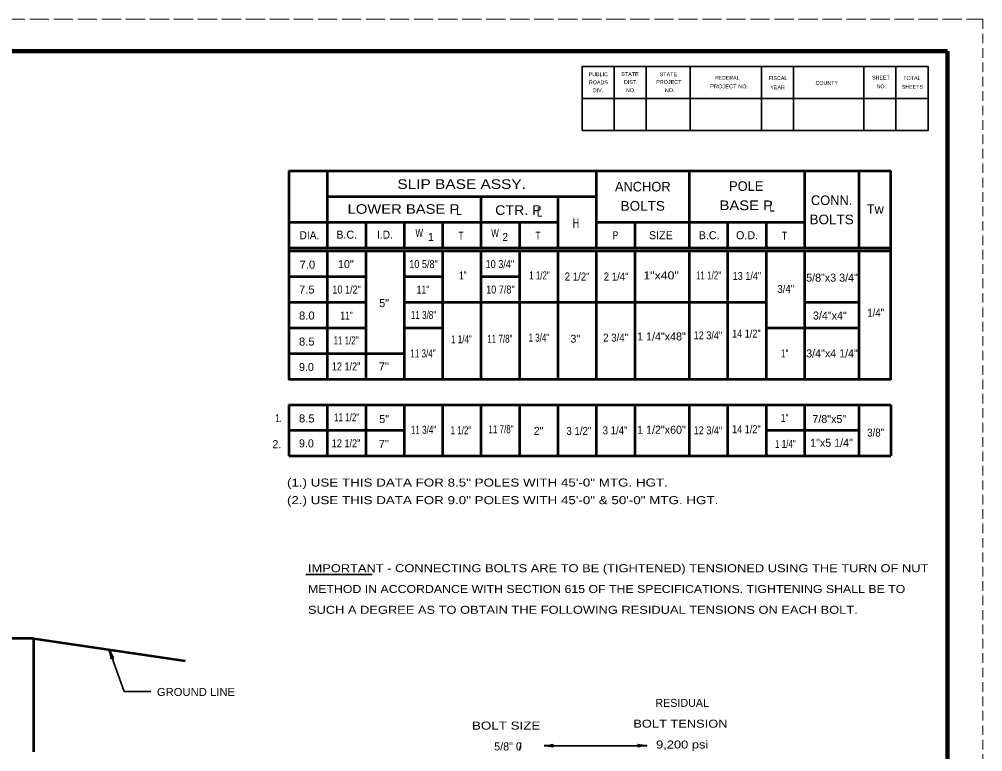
# Model space of a CAD drawing. Extents: x -2 to 678, y 0 to 440.
# Drawn here: x 377.6 to 678.4, y 211.2 to 440 of the extents above; entities that cross this region are included whole.
import ezdxf
from ezdxf.enums import TextEntityAlignment as Align

# ---------------------------------------------------------------- set-up
doc = ezdxf.new("R2010")
doc.units = 0
doc.linetypes.add('LONG_DASHED', pattern=[7.5, 6, -1.5])
doc.linetypes.add('MEDIUM_DASHED', pattern=[4.5, 3, -1.5])
doc.layers.add('1', color=7, linetype='Continuous', lineweight=53)
doc.layers.add('61', color=7, linetype='Continuous', lineweight=35)

msp = doc.modelspace()

# ---------------------------------------------------------------- linework, layer by layer
at = {"layer": '1', "linetype": 'MEDIUM_DASHED', "lineweight": 13}
msp.add_line((678.423, 439.973), (678.403, -0.047), dxfattribs=at)
at = {"layer": '1'}
for p, q in [((461.784, 392.615), (649.784, 392.615)), ((473.784, 392.615), (473.784, 368.615)), ((557.784, 392.615), (557.784, 368.615)), ((586.784, 392.615), (586.784, 368.615)), ((622.784, 392.615), (622.784, 368.615)), ((639.784, 392.615), (639.784, 368.615)), ((473.784, 384.615), (557.784, 384.615)), ((521.784, 384.615), (521.784, 368.615)), ((545.784, 384.615), (545.784, 368.615)), ((461.784, 376.615), (545.784, 376.615)), ((485.784, 376.615), (485.784, 368.615)), ((497.784, 376.615), (497.784, 368.615)), ((509.784, 376.615), (509.784, 368.615)), ((533.784, 376.615), (533.784, 368.615)), ((557.784, 376.615), (622.784, 376.615)), ((569.784, 376.615), (569.784, 368.615)), ((598.784, 376.615), (598.784, 368.615)), ((610.784, 376.615), (610.784, 368.615)), ((461.784, 368.615), (649.784, 368.615)), ((461.784, 367.615), (649.784, 367.615)), ((473.784, 367.615), (473.784, 327.615)), ((485.784, 367.615), (485.784, 327.615)), ((497.784, 367.615), (497.784, 327.615)), ((509.784, 367.615), (509.784, 327.615)), ((521.784, 367.615), (521.784, 327.615)), ((533.784, 367.615), (533.784, 327.615)), ((545.784, 367.615), (545.784, 327.615)), ((557.784, 367.615), (557.784, 327.615)), ((569.784, 367.615), (569.784, 327.615)), ((586.784, 367.615), (586.784, 327.615)), ((598.784, 367.615), (598.784, 327.615)), ((610.784, 367.615), (610.784, 327.615)), ((622.784, 367.615), (622.784, 327.615)), ((639.784, 367.615), (639.784, 327.615)), ((461.784, 359.615), (485.784, 359.615)), ((497.784, 359.615), (509.784, 359.615)), ((521.784, 359.615), (533.784, 359.615)), ((461.784, 351.615), (485.784, 351.615)), ((497.784, 351.615), (610.784, 351.615)), ((622.784, 351.615), (639.784, 351.615)), ((461.784, 343.615), (485.784, 343.615)), ((497.784, 343.615), (509.784, 343.615)), ((610.784, 343.615), (639.784, 343.615)), ((461.784, 319.615), (649.784, 319.615)), ((461.784, 319.615), (461.784, 303.615)), ((473.784, 319.615), (473.784, 303.615)), ((485.784, 319.615), (485.784, 303.615)), ((497.784, 319.615), (497.784, 303.615)), ((509.784, 319.615), (509.784, 303.615)), ((521.784, 319.615), (521.784, 303.615)), ((533.784, 319.615), (533.784, 303.615)), ((545.784, 319.615), (545.784, 303.615)), ((557.784, 319.615), (557.784, 303.615)), ((569.784, 319.615), (569.784, 303.615)), ((586.784, 319.615), (586.784, 303.615)), ((598.784, 319.615), (598.784, 303.615)), ((610.784, 319.615), (610.784, 303.615)), ((622.784, 319.615), (622.784, 303.615)), ((639.784, 319.615), (639.784, 303.615)), ((649.784, 319.615), (649.784, 303.615)), ((461.784, 311.615), (497.784, 311.615)), ((610.784, 311.615), (639.784, 311.615)), ((461.784, 303.615), (649.784, 303.615)), ((382.08, 246.576), (363.472, 246.576)), ((382.08, 246.576), (429.388, 239.606)), ((382.08, 246.576), (382.08, 211.231))]:
    msp.add_line(p, q, dxfattribs=at)
at = {"layer": '1', "lineweight": 35}
for p, q in [((467.139, 266.568), (487.803, 266.568)), ((541.511, 213.123), (573.511, 213.123))]:
    msp.add_line(p, q, dxfattribs=at)
at = {"layer": '1'}
for points in [[(461.784, 392.615), (461.784, 327.615), (649.784, 327.615), (649.784, 392.615)], [(461.784, 335.615), (485.784, 335.615), (497.784, 335.615)]]:
    msp.add_lwpolyline(points, dxfattribs=at)
at = {"layer": '1', "lineweight": 35}
msp.add_lwpolyline([(405.734, 243.091), (410.419, 230.073), (418.7, 230.073)], dxfattribs=at)
at = {"layer": '1', "lineweight": 40}
for centre, major_axis, ratio, start_param, end_param in [((405.914, 241.965), (-0.429, 1.712), 0.07063, 3.1407148, 5.41811), ((406.363, 242.158), (-0.752, 1.627), 0.122415, 0.8963533, 3.1415927), ((542.631, 212.911), (1.756, -0.176), 0.07063, 6.2823074, 8.5597026), ((542.631, 212.911), (1.756, -0.176), 0.07063, 6.2823074, 8.5597026), ((542.602, 213.399), (-1.786, -0.156), 0.122415, 0.8963533, 3.1415927), ((542.602, 213.399), (-1.786, -0.156), 0.122415, 0.8963533, 3.1415927), ((572.42, 212.846), (1.786, 0.156), 0.122415, 0.8963533, 3.1415927), ((572.39, 213.334), (-1.756, 0.176), 0.07063, 6.2823074, 8.5597026)]:
    msp.add_ellipse(centre, major_axis=major_axis, ratio=ratio, start_param=start_param, end_param=end_param, dxfattribs=at)
at = {"layer": '61', "linetype": 'LONG_DASHED', "lineweight": 13}
msp.add_line((-1.597, 439.973), (678.423, 439.973), dxfattribs=at)
at = {"layer": '61', "lineweight": 158}
msp.add_line((667.443, 429.973), (667.463, 9.933), dxfattribs=at)
at = {"layer": '61'}
for p, q in [((563.363, 425.213), (563.363, 405.213)), ((573.363, 425.213), (573.363, 405.213)), ((587.043, 425.213), (587.043, 405.213)), ((609.363, 425.213), (609.363, 405.213)), ((619.363, 425.213), (619.363, 405.213)), ((641.343, 425.233), (641.343, 405.233)), ((651.343, 425.233), (651.343, 405.233)), ((661.363, 415.193), (553.343, 415.213))]:
    msp.add_line(p, q, dxfattribs=at)
at = {"layer": '61', "lineweight": 158}
msp.add_lwpolyline([(667.443, 429.973), (28.403, 429.973), (28.403, 9.953)], dxfattribs=at)
at = {"layer": '61'}
for points in [[(661.343, 425.233), (553.363, 425.213), (553.363, 405.213)], [(661.343, 425.233), (661.343, 405.233), (553.363, 405.213)]]:
    msp.add_lwpolyline(points, dxfattribs=at)

# ---------------------------------------------------------------- texts
at = {"layer": '1'}
for s, height, width, p in [('SLIP BASE ASSY.', 3, 1.2, (495.679, 386.995)), ('LOWER BASE P', 3, 1.15, (480.145, 379.225)), ('L', 3, 0.75, (611.829, 379.931)), ('L', 3, 0.75, (514.037, 378.872)), ('CTR. P', 3, 1.1, (526.217, 378.872)), ('L', 3, 0.75, (539.279, 378.342)), ('H', 3, 0.7, (550.4, 374.81)), ('DIA.', 2.5, 0.95, (465.141, 371.278)), ('I.D.', 2.5, 0.95, (489.324, 371.455)), ('W', 2.5, 0.75, (501.327, 371.984)), ('T', 2.5, 0.8, (514.743, 371.101)), ('W', 2.5, 0.75, (524.981, 371.984)), ('2', 2.5, 0.9, (528.511, 370.748)), ('T', 2.5, 0.8, (538.75, 371.101)), ('P', 2.5, 0.75, (562.933, 371.278)), ('T', 2.5, 0.8, (615.712, 371.101)), ('7.0', 2.5, 1.05, (465.141, 362.095)), ('10 5/8"', 2.5, 0.85, (499.386, 362.271)), ('10 3/4"', 2.5, 0.85, (523.216, 362.271)), ('1"', 2.5, 0.8, (514.919, 358.739)), ('1 1/2"', 2.5, 0.75, (536.808, 358.739)), ('2 1/2"', 2.5, 0.9, (547.929, 358.386)), ('2 1/4"', 2.5, 0.9, (560.108, 358.386)), ('1"x40"', 2.5, 1.15, (572.465, 358.739)), ('11 1/2"', 2.5, 0.75, (588.881, 358.739)), ('13 1/4"', 2.5, 0.85, (600.355, 358.563)), ('7.5', 2.5, 1.05, (464.964, 354.324)), ('10 1/2"', 2.5, 0.85, (475.379, 354.324)), ('11"', 2.5, 0.8, (501.68, 354.324)), ('10 7/8"', 2.5, 0.85, (523.392, 354.324)), ('3/4"', 2.5, 0.9, (614.3, 354.501)), ('11 3/8"', 2.5, 0.75, (499.915, 346.377)), ('1/4"', 2.5, 0.9, (642.367, 347.084)), ('8.0', 2.5, 1.05, (464.964, 346.201)), ('11"', 2.5, 0.8, (477.85, 346.201)), ('14 1/2"', 2.5, 0.85, (600.178, 340.55)), ('8.5', 2.5, 1.05, (464.964, 338.077)), ('11 1/2"', 2.5, 0.75, (475.732, 338.43)), ('1 1/4"', 2.5, 0.75, (512.448, 338.784)), ('11 7/8"', 2.5, 0.75, (523.745, 338.96)), ('1 3/4"', 2.5, 0.75, (536.631, 339.313)), ('2 3/4"', 2.5, 0.9, (559.932, 339.313)), ('12 3/4"', 2.5, 0.85, (588.175, 340.02)), ('11 3/4"', 2.5, 0.75, (499.739, 334.369)), ('1"', 2.5, 0.8, (615.359, 334.369)), ('12 1/2"', 2.5, 0.85, (475.202, 330.307)), ('7"', 2.5, 1.05, (489.854, 330.307)), ('1.', 2.5, 0.65, (457.602, 314.183)), ('8.5', 2.5, 1.05, (464.964, 314.06)), ('11 1/2"', 2.5, 0.75, (475.909, 314.413)), ('1"', 2.5, 0.8, (615.359, 314.236)), ('11 3/4"', 2.5, 0.75, (499.915, 310.528)), ('1 1/2"', 2.5, 0.75, (512.272, 310.351)), ('11 7/8"', 2.5, 0.75, (524.098, 310.704)), ('3 1/4"', 2.5, 0.9, (559.755, 310.351)), ('12 3/4"', 2.5, 0.85, (588.175, 310.351)), ('14 1/2"', 2.5, 0.85, (600.178, 310.704)), ('3 1/2"', 2.5, 0.9, (548.458, 310.174)), ('3/8"', 2.5, 0.9, (642.367, 309.645)), ('12 1/2"', 2.5, 0.85, (475.202, 306.289)), ('7"', 2.5, 1.05, (489.854, 306.113)), ('1 1/4"', 2.5, 0.75, (613.594, 306.113)), ('(1.) USE THIS DATA FOR 8.5" POLES WITH 45\'-0" MTG. HGT.', 2.5, 1.25, (461.204, 294.044)), ('(2.) USE THIS DATA FOR 9.0" POLES WITH 45\'-0" & 50\'-0" MTG. HGT. ', 2.5, 1.25, (461.204, 288.544)), ('IMPORTANT - CONNECTING BOLTS ARE TO BE (TIGHTENED) TENSIONED USING THE TURN OF NUT', 2.5, 1.2, (467.769, 267.303)), ('METHOD IN ACCORDANCE WITH SECTION 615 OF THE SPECIFICATIONS. TIGHTENING SHALL BE TO', 2.5, 1.15, (467.769, 260.803)), ('SUCH A DEGREE AS TO OBTAIN THE FOLLOWING RESIDUAL TENSIONS ON EACH BOLT.', 2.5, 1.2, (467.769, 254.303)), ('GROUND LINE', 2.5, 1.05, (420.593, 228.653))]:
    msp.add_text(s, height=height, dxfattribs=dict(at, width=width)).set_placement(p)
for s, height, p in [('ANCHOR', 3, (572.288, 386.2)), ('POLE', 3, (604.591, 386.376)), ('CONN.', 3, (631.246, 381.961)), ('RESIDUAL', 2.5, (584.594, 225.241)), ('5/8" 0', 2.5, (530.222, 211.639))]:
    msp.add_text(s, height=height, dxfattribs=at).set_placement(p, align=Align.CENTER)
for s, height, width, p in [('BOLTS', 3, 1.05, (572.288, 380.2)), ('BASE P', 3, 1.15, (604.591, 380.376)), ('BOLTS', 3, 1.05, (631.246, 375.961)), ('BOLT SIZE ', 2.5, 1.25, (530.222, 218.139)), ('BOLT TENSION ', 2.5, 1.2, (584.594, 218.741)), ('9,200 psi', 2.5, 1.2, (584.594, 212.241))]:
    msp.add_text(s, height=height, dxfattribs=dict(at, width=width)).set_placement(p, align=Align.CENTER)
for s, height, p in [('Tw', 3, (642.19, 379.225)), ('B.C.', 2.5, (476.615, 371.455)), ('1', 2.5, (505.211, 370.748)), ('SIZE', 2.5, (574.23, 371.278)), ('B.C.', 2.5, (589.764, 371.278)), ('O.D.', 2.5, (601.414, 371.278)), ('10"', 2.5, (477.144, 362.271)), ('5/8"x3 3/4"', 2.5, (623.302, 358.033)), ('5"', 2.5, (490.03, 350.086)), ('3/4"x4"', 2.5, (625.421, 346.201)), ('3"', 2.5, (549.694, 338.96)), ('1 1/4"x48"', 2.5, (570.523, 339.667)), ('3/4"x4 1/4"', 2.5, (623.302, 334.369)), ('9.0', 2.5, (464.964, 330.13)), ('5"', 2.5, (490.03, 313.883)), ('7/8"x5"', 2.5, (625.244, 313.883)), ('1 1/2"x60"', 2.5, (570.523, 310.528)), ('2"', 2.5, (538.22, 310.174)), ('2.', 2.5, (456.654, 306.027)), ('9.0', 2.5, (464.964, 306.289)), ('1"x5 1/4"', 2.5, (624.538, 306.466)), ('/', 2.5, (533.541, 211.576))]:
    msp.add_text(s, height=height, dxfattribs=at).set_placement(p)
at = {"layer": '61'}
for s, rotation, p in [('PUBLIC', 0.033, (555.403, 422.193)), ('FEDERAL', 0.007, (594.863, 421.073)), ('FISCAL', 359.942, (611.603, 421.013)), ('SHEET', 0.059, (643.863, 421.133)), ('ROADS', 0.124, (555.483, 419.673)), ('DIV.', 359.932, (556.683, 417.173)), ('DIST.', 0.056, (566.443, 419.753)), ('YEAR', 0.105, (612.123, 418.113)), ('COUNTY', 0.069, (626.223, 419.473)), ('SHEETS', 359.959, (653.143, 418.293))]:
    msp.add_text(s, height=1.201, rotation=rotation, dxfattribs=at).set_placement(p)
for s, rotation, width, p in [('STATE', 0.059, 1.05, (565.563, 422.253)), ('STATE', 0.059, 1.05, (577.563, 422.193)), ('TOTAL', 359.926, 1.05, (653.603, 420.993)), ('NO.', 359.852, 0.95, (567.023, 417.233)), ('PROJECT', 359.908, 1.05, (576.483, 419.773)), ('NO.', 0.225, 0.95, (579.223, 417.233)), ('PROJECT NO.', 359.922, 1.1, (593.323, 418.413)), ('NO.', 359.852, 0.95, (645.283, 418.413))]:
    msp.add_text(s, height=1.201, rotation=rotation, dxfattribs=dict(at, width=width)).set_placement(p)

doc.saveas('drawing.dxf')
